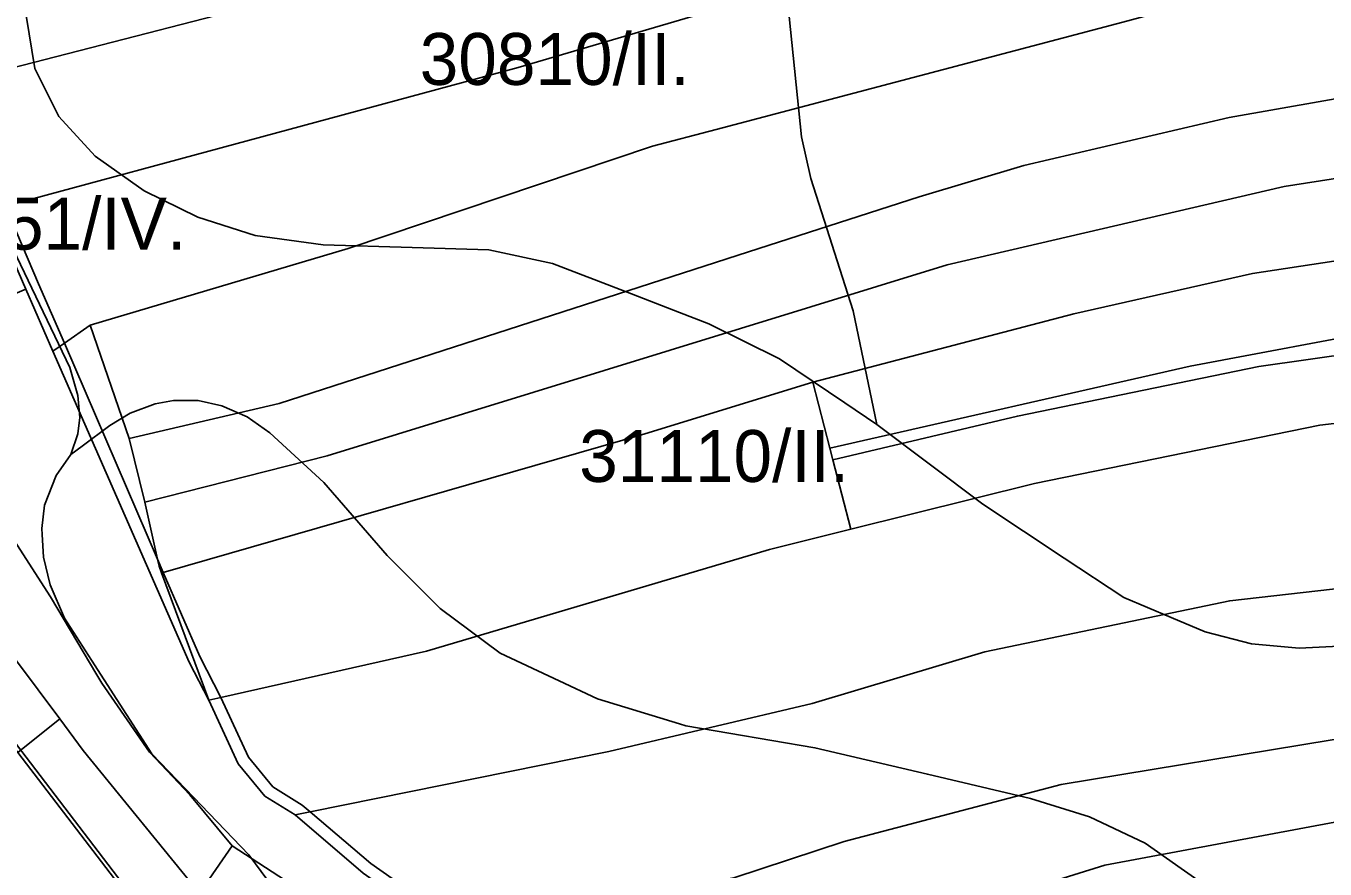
# Model space of a CAD drawing. Extents: x -535894 to -532827, y -1165802 to -1163635.
# Drawn here: x -535189 to -534813.3, y -1165071.2 to -1164827.4 of the extents above; entities that cross this region are included whole.
import ezdxf

# ---------------------------------------------------------------- set-up
doc = ezdxf.new("R2010")
doc.units = 0
for name, color, linetype in [('BPEJ_s', 7, 'Continuous'), ('orna_s', 7, 'Continuous'), ('ostatni_s', 7, 'Continuous'), ('trav_porost_s', 7, 'Continuous')]:
    doc.layers.add(name, color=color, linetype=linetype)

msp = doc.modelspace()

# ---------------------------------------------------------------- linework, layer by layer
at = {"layer": 'BPEJ_s'}
for points in [[(-535432.662, -1164773.563), (-535394.549, -1164753.205), (-535337.207, -1164722.574), (-535321.651, -1164717.756), (-535298.828, -1164711.653), (-535292.152, -1164708.42), (-535275.15, -1164716.09), (-535263.04, -1164725.17), (-535252.21, -1164738.55), (-535242.49, -1164754.951), (-535231.819, -1164785.06), (-535221.79, -1164822.33), (-535211.75, -1164849.56), (-535197.26, -1164882.69), (-535176.39, -1164926.18), (-535174, -1164934.22)], [(-535433.191, -1164773.846), (-535381.625, -1164819.757), (-535269.853, -1164932.956), (-535148.539, -1165091.751)], [(-535148.539, -1165091.751), (-535269.853, -1164932.956), (-535381.625, -1164819.757), (-535433.191, -1164773.846)], [(-535149, -1165092.96), (-535191.37, -1165037.5), (-535264.1, -1164942.33), (-535266.73, -1164938.9), (-535269.72, -1164935.43), (-535272.25, -1164932.85), (-535294.62, -1164910.11), (-535303.11, -1164901.49), (-535315.47, -1164888.93), (-535318.27, -1164886.08), (-535333.29, -1164870.81), (-535345.77, -1164858.11), (-535357.66, -1164846.04), (-535369, -1164834.5), (-535385.74, -1164817.49), (-535400.34, -1164804.75), (-535415.52, -1164791.51), (-535431.57, -1164777.51)], [(-534968.3, -1164824.6), (-534964.71, -1164859.4), (-534962.081, -1164871.5), (-534949.821, -1164909.73), (-534942.953, -1164942.645), (-534952.19, -1164936.387), (-534971.08, -1164923.59), (-534991.541, -1164913.492), (-535000, -1164910.221), (-535015.68, -1164904.16), (-535015.961, -1164904.051), (-535036.71, -1164896.031), (-535055.17, -1164892.088), (-535077.32, -1164891.41), (-535103.13, -1164890.62), (-535122.767, -1164887.929), (-535139.305, -1164882.655), (-535154.89, -1164875.01), (-535169.047, -1164864.965), (-535179.494, -1164853.513), (-535186.43, -1164839.65), (-535188.98, -1164824.36)], [(-535188.98, -1164824.36), (-535186.43, -1164839.65), (-535179.494, -1164853.513), (-535169.047, -1164864.965), (-535154.89, -1164875.01), (-535139.305, -1164882.655), (-535122.767, -1164887.929), (-535103.13, -1164890.62), (-535077.32, -1164891.41), (-535055.17, -1164892.088), (-535036.71, -1164896.031), (-535015.961, -1164904.051), (-535015.68, -1164904.16), (-535000, -1164910.221), (-534991.541, -1164913.492), (-534971.08, -1164923.59), (-534952.19, -1164936.387), (-534942.953, -1164942.645), (-534912.31, -1164965.64), (-534888.74, -1164981.25), (-534871.542, -1164992.642), (-534857.787, -1164998.444), (-534847.96, -1165002.59), (-534834.58, -1165006.09), (-534820.808, -1165007.363), (-534799.7, -1165006.25)], [(-534799.7, -1165006.25), (-534820.808, -1165007.363), (-534834.58, -1165006.09), (-534847.96, -1165002.59), (-534857.787, -1164998.444), (-534871.542, -1164992.642), (-534888.74, -1164981.25), (-534912.31, -1164965.64), (-534942.953, -1164942.645), (-534949.821, -1164909.73), (-534962.081, -1164871.5), (-534964.71, -1164859.4), (-534968.3, -1164824.6)], [(-535176.08, -1164951.26), (-535174.08, -1164945.29), (-535173.45, -1164940.59), (-535174, -1164934.22), (-535176.39, -1164926.18), (-535197.26, -1164882.69)], [(-535174, -1164934.22), (-535173.45, -1164940.59), (-535174.08, -1164945.29), (-535176.08, -1164951.26)], [(-535110.05, -1165086.73), (-535124.571, -1165067.131), (-535142.87, -1165048.02), (-535152.608, -1165037.849), (-535170.1, -1165010.75), (-535177.91, -1164998.65), (-535182.066, -1164989.044), (-535183.96, -1164980.97), (-535184.339, -1164974.424), (-535184.44, -1164972.69), (-535183.72, -1164965.92), (-535180.3, -1164957.4), (-535176.08, -1164951.26), (-535172.81, -1164948.87), (-535164.77, -1164942.9), (-535158.869, -1164939.32), (-535151.63, -1164936.61), (-535146.358, -1164935.645), (-535139.28, -1164935.73), (-535132.363, -1164937.234), (-535125.03, -1164940.43), (-535118.5, -1164945.05), (-535102.89, -1164959.39), (-535084.573, -1164980.567), (-535069.28, -1164995.86), (-535051.92, -1165008.759), (-535034.832, -1165016.773), (-535023.73, -1165021.98), (-535000, -1165029.25), (-534998.24, -1165029.79), (-534960.879, -1165036.126), (-534928.32, -1165043.8), (-534898.543, -1165050.818), (-534881.49, -1165056.07), (-534865.357, -1165063.694), (-534856.575, -1165069.901), (-534855.909, -1165070.372), (-534848.201, -1165075.82)], [(-534848.201, -1165075.82), (-534855.909, -1165070.372), (-534856.575, -1165069.901), (-534865.357, -1165063.694), (-534881.49, -1165056.07), (-534898.543, -1165050.818), (-534928.32, -1165043.8), (-534960.879, -1165036.126), (-534998.24, -1165029.79), (-535000, -1165029.25), (-535023.73, -1165021.98), (-535034.832, -1165016.773), (-535051.92, -1165008.759), (-535069.28, -1164995.86), (-535084.573, -1164980.567), (-535102.89, -1164959.39), (-535118.5, -1164945.05), (-535125.03, -1164940.43), (-535132.363, -1164937.234), (-535139.28, -1164935.73), (-535146.358, -1164935.645), (-535151.63, -1164936.61), (-535158.869, -1164939.32), (-535164.77, -1164942.9), (-535172.81, -1164948.87), (-535176.08, -1164951.26)], [(-535176.08, -1164951.26), (-535180.3, -1164957.4), (-535183.72, -1164965.92), (-535184.44, -1164972.69), (-535184.339, -1164974.424), (-535183.96, -1164980.97), (-535182.066, -1164989.044), (-535177.91, -1164998.65), (-535170.1, -1165010.75), (-535152.608, -1165037.849), (-535142.87, -1165048.02), (-535124.571, -1165067.131), (-535110.05, -1165086.73)]]:
    msp.add_lwpolyline(points, dxfattribs=at)
at = {"layer": 'orna_s'}
for points in [[(-534662.44, -1164677.22), (-534657.84, -1164675.77), (-534648.21, -1164691.35), (-534794.04, -1164738.9), (-534925.58, -1164776.38), (-534981.55, -1164786.79), (-535087.94, -1164812.37), (-535210.21, -1164843.9), (-535217.32, -1164826.11), (-535087.47, -1164795.57), (-534978.25, -1164770.31), (-534932.16, -1164761.71), (-534795.22, -1164722.3), (-534691.34, -1164686.36)], [(-534644.26, -1164706.72), (-534642.29, -1164732.8), (-534729.01, -1164753.95), (-534823.37, -1164779.94), (-534931.7, -1164805.53), (-535046.65, -1164839.34), (-535194.99, -1164879.49), (-535210.21, -1164843.9), (-535087.94, -1164812.37), (-534981.55, -1164786.79), (-534925.58, -1164776.38), (-534794.04, -1164738.9), (-534648.21, -1164691.35)], [(-534729.01, -1164753.95), (-534642.29, -1164732.8), (-534639.25, -1164772.83), (-534705.71, -1164784.93), (-534805.56, -1164808.33), (-534871.85, -1164826.25), (-534989.4, -1164857.3), (-535007.79, -1164862.16), (-535095.84, -1164891.7), (-535170.48, -1164913.86), (-535177.9, -1164919.08), (-535185.4, -1164901.91), (-535194.99, -1164879.49), (-535046.65, -1164839.34), (-534931.7, -1164805.53), (-534823.37, -1164779.94)], [(-534639.25, -1164772.83), (-534637.67, -1164793.79), (-534635.77, -1164799.17), (-534633.72, -1164804.95), (-534638.54, -1164823.25), (-534671.88, -1164825.83), (-534710.47, -1164830.87), (-534729.94, -1164834.28), (-534841.03, -1164853.81), (-534900.4, -1164867.67), (-534930.69, -1164876.79), (-534980.06, -1164892.73), (-535115.81, -1164936.57), (-535159.15, -1164946.66), (-535170.48, -1164913.86), (-535095.84, -1164891.7), (-535007.79, -1164862.16), (-534989.4, -1164857.3), (-534871.85, -1164826.25), (-534805.56, -1164808.33), (-534705.71, -1164784.93)], [(-534729.94, -1164834.28), (-534710.47, -1164830.87), (-534705.37, -1164856.07), (-534723.79, -1164857.99), (-534825.11, -1164873.81), (-534922.64, -1164896.44), (-535101.94, -1164951.67), (-535154.63, -1164965.06), (-535159.15, -1164946.66), (-535115.81, -1164936.57), (-534980.06, -1164892.73), (-534930.69, -1164876.79), (-534900.4, -1164867.67), (-534841.03, -1164853.81)], [(-534705.37, -1164856.07), (-534641.49, -1164849.43), (-534643.23, -1164857.71), (-534659.18, -1164861.96), (-534703.62, -1164873.54), (-534701.97, -1164880.31), (-534743.37, -1164885.15), (-534834.28, -1164898.95), (-534885.94, -1164910.64), (-534961.47, -1164930.35), (-535010.08, -1164945.35), (-535149.32, -1164985.4), (-535151, -1164981.54), (-535154.63, -1164965.06), (-535101.94, -1164951.67), (-534922.64, -1164896.44), (-534825.11, -1164873.81), (-534723.79, -1164857.99)], [(-534743.37, -1164885.15), (-534701.97, -1164880.31), (-534695.57, -1164904.53), (-534793.82, -1164914.8), (-534852.33, -1164925.8), (-534956.54, -1164949.5), (-534961.47, -1164930.35), (-534885.94, -1164910.64), (-534834.28, -1164898.95)], [(-534695.57, -1164904.53), (-534694, -1164910.49), (-534703.82, -1164910.78), (-534747.53, -1164913.81), (-534832.45, -1164925.81), (-534902.3, -1164940.2), (-534955.68, -1164952.84), (-534956.54, -1164949.5), (-534852.33, -1164925.8), (-534793.82, -1164914.8)], [(-534694, -1164910.49), (-534659.5, -1164909.46), (-534659.02, -1164930.05), (-534691.31, -1164930.67), (-534736.79, -1164933.73), (-534814.82, -1164942.8), (-534897.39, -1164959.74), (-534950.5, -1164972.92), (-534955.68, -1164952.84), (-534902.3, -1164940.2), (-534832.45, -1164925.81), (-534747.53, -1164913.81), (-534703.82, -1164910.78)], [(-535170.48, -1164913.86), (-535159.15, -1164946.66), (-535154.63, -1164965.06), (-535151, -1164981.54), (-535177.9, -1164919.08)], [(-534961.47, -1164930.35), (-534956.54, -1164949.5), (-534955.68, -1164952.84), (-534950.5, -1164972.92), (-534974.01, -1164978.76), (-535073.21, -1165008.15), (-535132.68, -1165021.61), (-535138.71, -1165009.74), (-535149.32, -1164985.4), (-535010.08, -1164945.35)], [(-534691.31, -1164930.67), (-534659.02, -1164930.05), (-534658.67, -1164944.77), (-534658.09, -1164968.25), (-534657.76, -1164976.32), (-534659.02, -1164979.39), (-534688.38, -1164981.11), (-534776.34, -1164986.27), (-534840.9, -1164993.6), (-534911.68, -1165008.4), (-534961.7, -1165023.3), (-535020.48, -1165037.2), (-535106.82, -1165054.65), (-535109.11, -1165052.7), (-535117.6, -1165047.48), (-535124.68, -1165038.88), (-535132.68, -1165021.61), (-535073.21, -1165008.15), (-534974.01, -1164978.76), (-534950.5, -1164972.92), (-534897.39, -1164959.74), (-534814.82, -1164942.8), (-534736.79, -1164933.73)], [(-534688.38, -1164981.11), (-534659.02, -1164979.39), (-534659.81, -1164981.95), (-534655.57, -1165032.56), (-534724.66, -1165029.47), (-534765.23, -1165030.38), (-534811.29, -1165033.87), (-534889.63, -1165046.79), (-534952.44, -1165063.23), (-534984.36, -1165073.72), (-535013.06, -1165078.91), (-535040.34, -1165080.81), (-535067.25, -1165085.28), (-535068.17, -1165084.42), (-535089.33, -1165069.61), (-535106.82, -1165054.65), (-535020.48, -1165037.2), (-534961.7, -1165023.3), (-534911.68, -1165008.4), (-534840.9, -1164993.6), (-534776.34, -1164986.27)], [(-534765.23, -1165030.38), (-534724.66, -1165029.47), (-534655.57, -1165032.56), (-534654.53, -1165060.65), (-534677.01, -1165058.08), (-534733.66, -1165051.62), (-534773.14, -1165052.16), (-534797.08, -1165055.15), (-534876.98, -1165070.12), (-534985.58, -1165103.95), (-535010.28, -1165108.81), (-535038.78, -1165114.13), (-535054.81, -1165096.75), (-535067.25, -1165085.28), (-535040.34, -1165080.81), (-535013.06, -1165078.91), (-534984.36, -1165073.72), (-534952.44, -1165063.23), (-534889.63, -1165046.79), (-534811.29, -1165033.87)]]:
    msp.add_lwpolyline(points, close=True, dxfattribs=at)
msp.add_lwpolyline([(-534985.58, -1165103.95), (-534876.98, -1165070.12), (-534797.08, -1165055.15), (-534773.14, -1165052.16), (-534733.66, -1165051.62), (-534677.01, -1165058.08), (-534654.53, -1165060.65), (-534656.31, -1165088.09)], dxfattribs=at)
at = {"layer": 'ostatni_s'}
for points in [[(-535198.89, -1164880.55), (-535194.99, -1164879.49), (-535185.4, -1164901.91), (-535177.9, -1164919.08), (-535181.28, -1164921.44), (-535189.08, -1164903.47), (-535191.25, -1164898.41)], [(-535177.9, -1164919.08), (-535151, -1164981.54), (-535150.55, -1164983.6), (-535149.83, -1164985.54), (-535136.18, -1165022.4), (-535141.82, -1165011.33), (-535181.28, -1164921.44)], [(-535150.55, -1164983.6), (-535151, -1164981.54), (-535149.32, -1164985.4), (-535149.83, -1164985.54)], [(-535149.32, -1164985.4), (-535138.71, -1165009.74), (-535132.68, -1165021.61), (-535136.18, -1165022.4), (-535149.83, -1164985.54)], [(-535136.18, -1165022.4), (-535132.68, -1165021.61), (-535124.68, -1165038.88), (-535117.6, -1165047.48), (-535109.11, -1165052.7), (-535106.82, -1165054.65), (-535111.17, -1165055.54), (-535119.93, -1165050.16), (-535127.67, -1165040.76)], [(-535111.17, -1165055.54), (-535106.82, -1165054.65), (-535089.33, -1165069.61), (-535068.17, -1165084.42), (-535067.25, -1165085.28), (-535071.93, -1165086.06), (-535091.48, -1165072.37)]]:
    msp.add_lwpolyline(points, close=True, dxfattribs=at)
at = {"layer": 'trav_porost_s'}
msp.add_lwpolyline([(-535102.38, -1165082.03), (-535129.39, -1165064.5), (-535141.65, -1165049.71), (-535153.27, -1165037.38), (-535167.09, -1165017.44), (-535168.5, -1165015.08), (-535181.9, -1164992.48), (-535192.57, -1164975.97), (-535220.19, -1164916.49), (-535189.08, -1164903.47), (-535181.28, -1164921.44), (-535141.82, -1165011.33), (-535136.18, -1165022.4), (-535127.67, -1165040.76), (-535119.93, -1165050.16), (-535111.17, -1165055.54), (-535091.48, -1165072.37)], dxfattribs=at)
for points in [[(-535220.19, -1164916.49), (-535192.57, -1164975.97), (-535181.9, -1164992.48), (-535168.5, -1165015.08), (-535167.09, -1165017.44), (-535153.27, -1165037.38), (-535141.65, -1165049.71), (-535129.39, -1165064.5), (-535138.85, -1165078.22), (-535172.47, -1165036.89), (-535179.28, -1165027.8), (-535211.27, -1164985.05), (-535243.3, -1164928.03), (-535231.36, -1164922.07)], [(-535243.3, -1164928.03), (-535211.27, -1164985.05), (-535179.28, -1165027.8), (-535191.37, -1165037.5), (-535264.1, -1164942.33)], [(-535179.28, -1165027.8), (-535172.47, -1165036.89), (-535138.85, -1165078.22), (-535141.75, -1165082.45), (-535149, -1165092.96), (-535191.37, -1165037.5)], [(-535138.85, -1165078.22), (-535129.39, -1165064.5), (-535102.38, -1165082.03), (-535080.8, -1165098.36), (-535076.07, -1165102.38), (-535091.8, -1165120.03), (-535141.75, -1165082.45)]]:
    msp.add_lwpolyline(points, close=True, dxfattribs=at)

# ---------------------------------------------------------------- texts
at = {"layer": 'BPEJ_s'}
for s, p in [('30810/II.', (-535075.156, -1164844.397)), ('32451/IV.', (-535228.576, -1164892.05)), ('31110/II.', (-535029.041, -1164959.242))]:
    msp.add_text(s, height=15, dxfattribs=at).set_placement(p)

doc.saveas('drawing.dxf')
